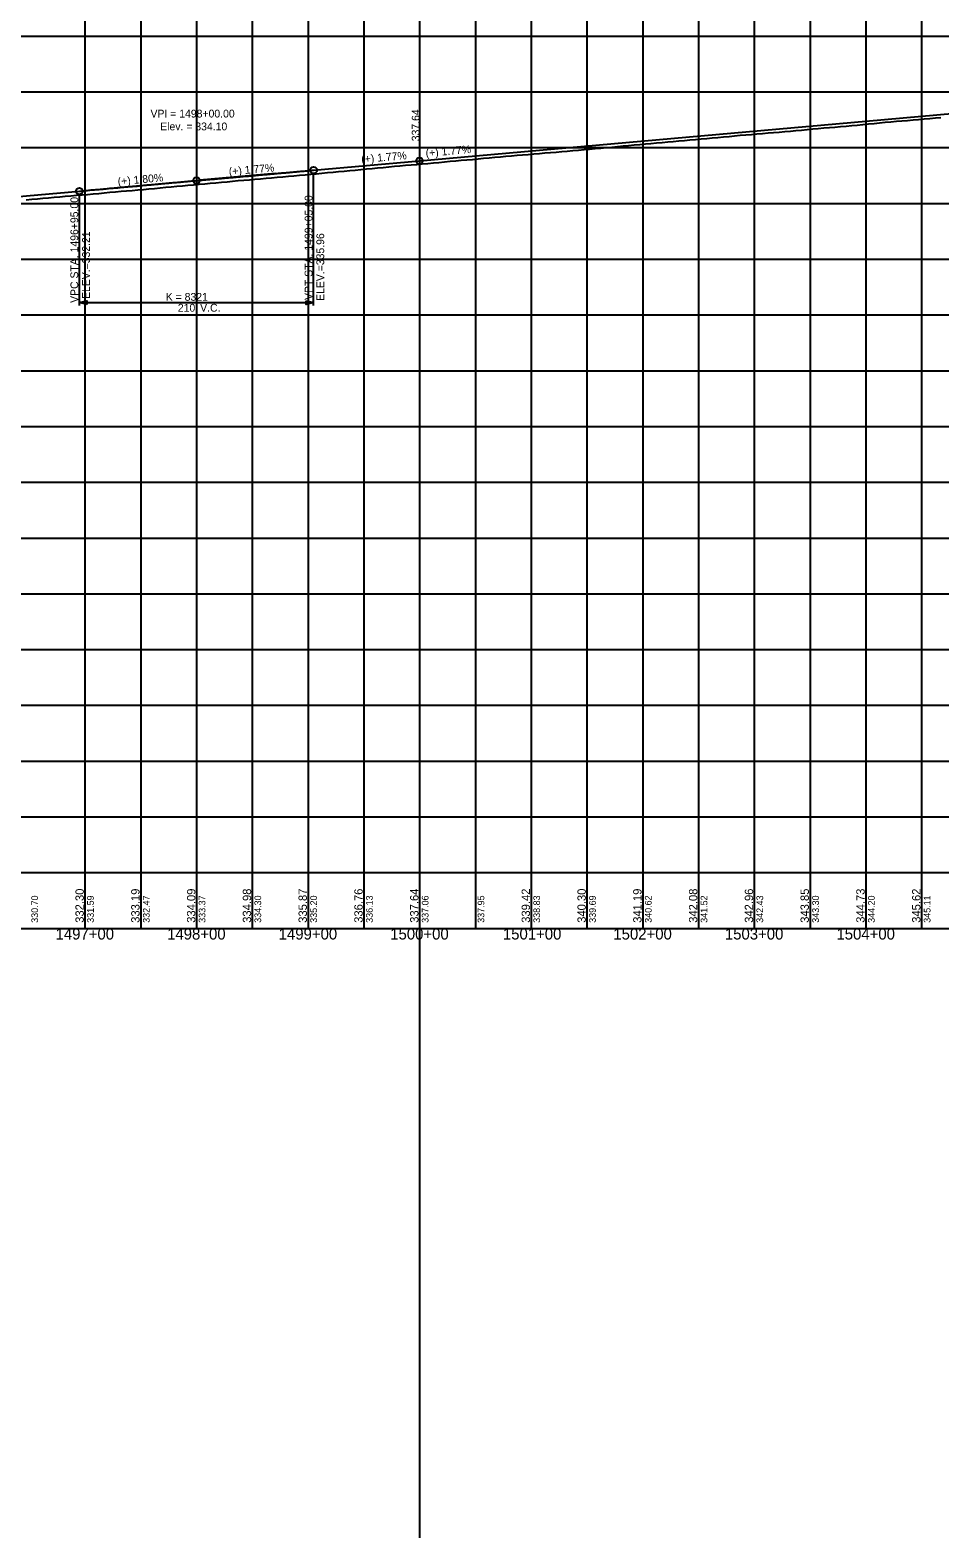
# Model space of a CAD drawing. Extents: x -90830 to 2015517, y -20856 to 836331.
# Drawn here: x 38574 to 39390, y -11344 to -9992 of the extents above; entities that cross this region are included whole.
import ezdxf

# ---------------------------------------------------------------- set-up
doc = ezdxf.new("R2010")
doc.units = 0
for name, color, linetype in [('Level 1', 7, 'Continuous'), ('RD_DDB_GradeTX', 7, 'Continuous'), ('RD_DDB_Profile_Elev', 7, 'Continuous'), ('RD_DDB_Profile_EX', 7, 'Continuous'), ('RD_DDB_Profile_Lbl', 7, 'Continuous'), ('RD_DDB_Profile_PR', 7, 'Continuous'), ('RD_DDB_StaTX', 7, 'Continuous'), ('RD_DDB_StripGrade', 7, 'Continuous'), ('RD_DDB_VCLbl', 7, 'Continuous'), ('RD_GPK_Profile_Cell', 7, 'Continuous'), ('RD_TX_Drainage', 7, 'Continuous')]:
    doc.layers.add(name, color=color, linetype=linetype)

msp = doc.modelspace()

# ---------------------------------------------------------------- linework, layer by layer
at = {"layer": 'Level 1'}
for p, q in [((38923.5, -3180.8), (38923.5, -11343.5)), ((38623.5, -9797.1), (38623.5, -10297.1)), ((38673.5, -9797.1), (38673.5, -10297.1)), ((38723.5, -9797.1), (38723.5, -10297.1)), ((38773.5, -9797.1), (38773.5, -10297.1)), ((38823.5, -9797.1), (38823.5, -10297.1)), ((38873.5, -9797.1), (38873.5, -10297.1)), ((38923.5, -9797.1), (38923.5, -10297.1)), ((38973.5, -9797.1), (38973.5, -10297.1)), ((39023.5, -9797.1), (39023.5, -10297.1)), ((39073.5, -9797.1), (39073.5, -10297.1)), ((39123.5, -9797.1), (39123.5, -10297.1)), ((39173.5, -9797.1), (39173.5, -10297.1)), ((39223.5, -9797.1), (39223.5, -10297.1)), ((39273.5, -9797.1), (39273.5, -10297.1)), ((39323.5, -9797.1), (39323.5, -10297.1)), ((39373.5, -9797.1), (39373.5, -10297.1)), ((38373.5, -9997.1), (39973.5, -9997.1)), ((38373.5, -10047.1), (39973.5, -10047.1)), ((38373.5, -10097.1), (39973.5, -10097.1)), ((38373.5, -10147.1), (39973.5, -10147.1)), ((38373.5, -10197.1), (39973.5, -10197.1)), ((38373.5, -10247.1), (39973.5, -10247.1)), ((38373.5, -10297.1), (39973.5, -10297.1)), ((38373.5, -10297.1), (39973.5, -10297.1)), ((38623.5, -10297.1), (38623.5, -10797.1)), ((38673.5, -10297.1), (38673.5, -10797.1)), ((38723.5, -10297.1), (38723.5, -10797.1)), ((38773.5, -10297.1), (38773.5, -10797.1)), ((38823.5, -10297.1), (38823.5, -10797.1)), ((38873.5, -10297.1), (38873.5, -10797.1)), ((38923.5, -10297.1), (38923.5, -10797.1)), ((38973.5, -10297.1), (38973.5, -10797.1)), ((39023.5, -10297.1), (39023.5, -10797.1)), ((39073.5, -10297.1), (39073.5, -10797.1)), ((39123.5, -10297.1), (39123.5, -10797.1)), ((39173.5, -10297.1), (39173.5, -10797.1)), ((39223.5, -10297.1), (39223.5, -10797.1)), ((39273.5, -10297.1), (39273.5, -10797.1)), ((39323.5, -10297.1), (39323.5, -10797.1)), ((39373.5, -10297.1), (39373.5, -10797.1)), ((38373.5, -10347.1), (39973.5, -10347.1)), ((38373.5, -10397.1), (39973.5, -10397.1)), ((38373.5, -10447.1), (39973.5, -10447.1)), ((38373.5, -10497.1), (39973.5, -10497.1)), ((38373.5, -10547.1), (39973.5, -10547.1)), ((38373.5, -10597.1), (39973.5, -10597.1)), ((38373.5, -10647.1), (39973.5, -10647.1)), ((38373.5, -10697.1), (39973.5, -10697.1)), ((38373.5, -10747.1), (39973.5, -10747.1)), ((38373.5, -10797.1), (39973.5, -10797.1))]:
    msp.add_line(p, q, dxfattribs=at)
at = {"layer": 'RD_DDB_GradeTX'}
for p, q in [((38794.2, -10120.4), (38726.4, -10126.4)), ((38652.7, -10133), (38720.5, -10126.9))]:
    msp.add_line(p, q, dxfattribs=at)
for centre in [(38923.5, -10108.9), (38723.5, -10126.6)]:
    msp.add_circle(centre, 3, dxfattribs=at)
at = {"layer": 'RD_DDB_Profile_EX'}
for points in [[(38920.9, -10112.1), (38925.9, -10111.6), (38930.9, -10111.2), (38935.9, -10110.7), (38940.9, -10110.3), (38945.9, -10109.8), (38950.9, -10109.3), (38955.9, -10108.8), (38960.9, -10108.4), (38965.9, -10108), (38970.9, -10107.6), (38975.9, -10107.2), (38980.9, -10106.7), (38985.9, -10106.3), (38990.9, -10105.8), (38995.9, -10105.4), (39000.9, -10104.9), (39005.9, -10104.5), (39010.9, -10104), (39015.9, -10103.6), (39020.9, -10103.2), (39025.9, -10102.7), (39030.9, -10102.3), (39035.9, -10101.9), (39040.9, -10101.5), (39045.9, -10101.1), (39050.9, -10100.7), (39055.9, -10100.3), (39060.9, -10099.8), (39065.9, -10099.3), (39070.9, -10098.9), (39075.9, -10098.4), (39080.9, -10098), (39085.9, -10097.5), (39090.9, -10097), (39095.9, -10096.6), (39100.9, -10096.1), (39105.9, -10095.6), (39110.9, -10095.2), (39115.9, -10094.7), (39120.9, -10094.2), (39125.9, -10093.8), (39130.9, -10093.3), (39135.9, -10092.8), (39140.9, -10092.4), (39145.9, -10092), (39150.9, -10091.5), (39155.9, -10091.1), (39160.9, -10090.7), (39165.9, -10090.2), (39170.9, -10089.7), (39175.9, -10089.3), (39180.9, -10088.8), (39185.9, -10088.3), (39190.9, -10087.9), (39195.9, -10087.4), (39200.9, -10087), (39205.9, -10086.5), (39210.9, -10086), (39215.9, -10085.6), (39220.9, -10085.2), (39225.9, -10084.8), (39230.9, -10084.3), (39235.9, -10083.9), (39240.9, -10083.5), (39245.9, -10083.1), (39250.9, -10082.6), (39255.9, -10082.2), (39260.9, -10081.8), (39265.9, -10081.3), (39270.9, -10080.8), (39275.9, -10080.4), (39280.9, -10080), (39285.9, -10079.5), (39290.9, -10079.1), (39295.9, -10078.7), (39300.9, -10078.2), (39305.9, -10077.8), (39310.9, -10077.3), (39315.9, -10076.9), (39320.9, -10076.4), (39325.9, -10075.9), (39330.9, -10075.4), (39335.9, -10074.9), (39340.9, -10074.4), (39345.9, -10074), (39350.9, -10073.5), (39355.9, -10073.1), (39360.9, -10072.7), (39365.9, -10072.2), (39370.9, -10071.8), (39375.9, -10071.4), (39380.9, -10070.9), (39385.9, -10070.4), (39390.9, -10070)], [(38570.9, -10143.9), (38575.9, -10143.4), (38580.9, -10142.9), (38585.9, -10142.5), (38590.9, -10142), (38595.9, -10141.5), (38600.9, -10141.1), (38605.9, -10140.7), (38610.9, -10140.3), (38615.9, -10139.8), (38620.9, -10139.4), (38625.9, -10139), (38630.9, -10138.5), (38635.9, -10138.1), (38640.9, -10137.6), (38645.9, -10137.1), (38650.9, -10136.6), (38655.9, -10136.2), (38660.9, -10135.8), (38665.9, -10135.4), (38670.9, -10135), (38675.9, -10134.5), (38680.9, -10134.1), (38685.9, -10133.6), (38690.9, -10133.1), (38695.9, -10132.7), (38700.9, -10132.2), (38705.9, -10131.8), (38710.9, -10131.3), (38715.9, -10130.9), (38720.9, -10130.5), (38725.9, -10130), (38730.9, -10129.6), (38735.9, -10129.1), (38740.9, -10128.7), (38745.9, -10128.2), (38750.9, -10127.7), (38755.9, -10127.2), (38760.9, -10126.7), (38765.9, -10126.3), (38770.9, -10125.9), (38775.9, -10125.4), (38780.9, -10125), (38785.9, -10124.6), (38790.9, -10124.1), (38795.9, -10123.7), (38800.9, -10123.2), (38805.9, -10122.7), (38810.9, -10122.3), (38815.9, -10121.8), (38820.9, -10121.4), (38825.9, -10120.9), (38830.9, -10120.5), (38835.9, -10120), (38840.9, -10119.5), (38845.9, -10119.1), (38850.9, -10118.6), (38855.9, -10118.1), (38860.9, -10117.6), (38865.9, -10117.2), (38870.9, -10116.7), (38875.9, -10116.2), (38880.9, -10115.7), (38885.9, -10115.2), (38890.9, -10114.8), (38895.9, -10114.3), (38900.9, -10113.8), (38905.9, -10113.4), (38910.9, -10112.9), (38915.9, -10112.5), (38920.9, -10112.1)]]:
    msp.add_lwpolyline(points, dxfattribs=at)
at = {"layer": 'RD_DDB_Profile_PR'}
for p, q in [((39323.5, -10073.4), (39421, -10064.8)), ((38923.5, -10108.9), (39323.5, -10073.4)), ((38828.5, -10117.3), (38923.5, -10108.9)), ((36708.5, -10307.8), (38618.5, -10136.1))]:
    msp.add_line(p, q, dxfattribs=at)
msp.add_spline([(38618.5, -10136.1), (38622.7, -10135.7), (38626.9, -10135.3), (38631.1, -10134.9), (38635.3, -10134.6), (38639.5, -10134.2), (38643.7, -10133.8), (38647.9, -10133.4), (38652.1, -10133.1), (38656.3, -10132.7), (38660.5, -10132.3), (38664.7, -10131.9), (38668.9, -10131.6), (38673.1, -10131.2), (38677.3, -10130.8), (38681.5, -10130.4), (38685.7, -10130.1), (38689.9, -10129.7), (38694.1, -10129.3), (38698.3, -10128.9), (38702.5, -10128.5), (38706.7, -10128.2), (38710.9, -10127.8), (38715.1, -10127.4), (38719.3, -10127), (38723.5, -10126.7), (38727.7, -10126.3), (38731.9, -10125.9), (38736.1, -10125.5), (38740.3, -10125.2), (38744.5, -10124.8), (38748.7, -10124.4), (38752.9, -10124), (38757.1, -10123.7), (38761.3, -10123.3), (38765.5, -10122.9), (38769.7, -10122.6), (38773.9, -10122.2), (38778.1, -10121.8), (38782.3, -10121.4), (38786.5, -10121.1), (38790.7, -10120.7), (38794.9, -10120.3), (38799.1, -10119.9), (38803.3, -10119.6), (38807.5, -10119.2), (38811.7, -10118.8), (38815.9, -10118.4), (38820.1, -10118.1), (38824.3, -10117.7), (38828.5, -10117.3)], degree=3, dxfattribs=at)
at = {"layer": 'RD_DDB_VCLbl'}
for p, q in [((38828.5, -10238.6), (38828.5, -10120.3)), ((38618.5, -10238.6), (38618.5, -10139.1)), ((38618.5, -10236.1), (38828.5, -10236.1))]:
    msp.add_line(p, q, dxfattribs=at)
for centre in [(38828.5, -10117.3), (38618.5, -10136.1)]:
    msp.add_circle(centre, 3, dxfattribs=at)
at = {"layer": 'RD_GPK_Profile_Cell'}
msp.add_line((4823.5, -10797.1), (75223.5, -10797.1), dxfattribs=at)
at = {"layer": 'RD_TX_Drainage'}
for points in [[(38625.1, -10237.7), (38618.5, -10236.1), (38625.1, -10234.4)], [(38821.9, -10234.4), (38828.5, -10236.1), (38821.9, -10237.7)]]:
    msp.add_lwpolyline(points, close=True, dxfattribs=at)

# ---------------------------------------------------------------- texts
at = {"layer": 'RD_DDB_GradeTX'}
for s, rotation, p in [('(+) 1.77%', 5.0664, (38929.2, -10105.5)), ('(+) 1.77%', 5.0664, (38871.5, -10111)), ('(+) 1.80%', 5.1381, (38653.2, -10130.9)), ('(+) 1.77%', 5.0664, (38752.8, -10122))]:
    msp.add_text(s, height=7, rotation=rotation, dxfattribs=at).set_placement(p)
at = {"layer": 'RD_DDB_Profile_Elev'}
for s, p in [('332.30', (38622.5, -10792.1)), ('333.19', (38672.5, -10792.1)), ('334.09', (38722.5, -10792.1)), ('334.98', (38772.5, -10792.1)), ('335.87', (38822.5, -10792.1)), ('336.76', (38872.5, -10792.1)), ('337.64', (38922.5, -10792.1)), ('339.42', (39022.5, -10792.1)), ('340.30', (39072.5, -10792.1)), ('341.19', (39122.5, -10792.1)), ('342.08', (39172.5, -10792.1)), ('342.96', (39222.5, -10792.1)), ('343.85', (39272.5, -10792.1)), ('344.73', (39322.5, -10792.1)), ('345.62', (39372.5, -10792.1))]:
    msp.add_text(s, height=7.5, rotation=90, dxfattribs=at).set_placement(p)
at = {"layer": 'RD_DDB_Profile_Lbl'}
for s, p in [('VPI = 1498+00.00', (38682.3, -10070.1)), ('Elev. = 334.10', (38691, -10081.6))]:
    msp.add_text(s, height=7, dxfattribs=at).set_placement(p)
msp.add_text('337.64', height=7, rotation=90, dxfattribs=at).set_placement((38923.5, -10091.4))
at = {"layer": 'RD_DDB_StaTX'}
for s, p in [('1497+00', (38597.2, -10807.1)), ('1498+00', (38697.2, -10807.1)), ('1499+00', (38797.2, -10807.1)), ('1500+00', (38897.2, -10807.1)), ('1501+00', (38998.2, -10807.1)), ('1502+00', (39097.2, -10807.1)), ('1503+00', (39197.2, -10807.1)), ('1504+00', (39297.2, -10807.1))]:
    msp.add_text(s, height=10, dxfattribs=at).set_placement(p)
at = {"layer": 'RD_DDB_StripGrade'}
for s, height, p in [('VPC STA. 1496+95.00 ', 7, (38617.5, -10236.3)), ('VPT STA. 1499+05.00 ', 7, (38827.5, -10233.7)), ('ELEV.=332.21', 7, (38628, -10232.8)), ('ELEV.=335.96', 7, (38838, -10234.5)), ('330.70', 6, (38581.5, -10792.1)), ('331.59', 6, (38631.5, -10792.1)), ('332.47', 6, (38681.5, -10792.1)), ('333.37', 6, (38731.5, -10792.1)), ('334.30', 6, (38781.5, -10792.1)), ('335.20', 6, (38831.5, -10792.1)), ('336.13', 6, (38881.5, -10792.1)), ('337.06', 6, (38931.5, -10792.1)), ('337.95', 6, (38981.5, -10792.1)), ('338.83', 6, (39031.5, -10792.1)), ('339.69', 6, (39081.5, -10792.1)), ('340.62', 6, (39131.5, -10792.1)), ('341.52', 6, (39181.5, -10792.1)), ('342.43', 6, (39231.5, -10792.1)), ('343.30', 6, (39281.5, -10792.1)), ('344.20', 6, (39331.5, -10792.1)), ('345.11', 6, (39381.5, -10792.1))]:
    msp.add_text(s, height=height, rotation=90, dxfattribs=at).set_placement(p)
at = {"layer": 'RD_DDB_VCLbl'}
for s, p in [('K = 8321', (38696, -10234.4)), ("210' V.C.", (38706.8, -10244.2))]:
    msp.add_text(s, height=7, dxfattribs=at).set_placement(p)

doc.saveas('drawing.dxf')
